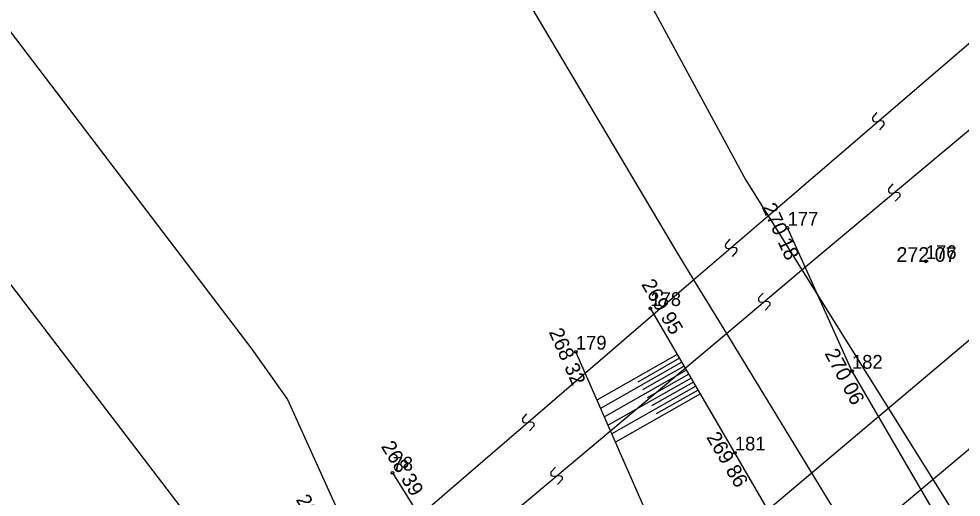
# Model space of a CAD drawing. Extents: x -492379 to -491966, y -1126153 to -1125860.
# Drawn here: x -492184.88 to -492154.06, y -1126013.22 to -1125997.58 of the extents above; entities that cross this region are included whole.
import ezdxf

# ---------------------------------------------------------------- set-up
doc = ezdxf.new("R2010")
doc.units = 0
for name, color, linetype in [('body', 7, 'Continuous'), ('hrana svahu', 7, 'Continuous'), ('katastrální mapa', 7, 'Continuous'), ('ostatní objekty', 7, 'Continuous'), ('podrobný výškový bod', 7, 'Continuous'), ('vodstvo', 7, 'Continuous'), ('výšky', 7, 'Continuous'), ('čísla bodů', 7, 'Continuous'), ('šrafy', 7, 'Continuous')]:
    doc.layers.add(name, color=color, linetype=linetype)

msp = doc.modelspace()

# ---------------------------------------------------------------- linework, layer by layer
at = {"layer": 'body'}
for p, q in [((-492159.736, -1126004.423), (-492159.736, -1126004.423)), ((-492155.216, -1126005.511), (-492155.216, -1126005.511)), ((-492164.225, -1126007.048), (-492164.225, -1126007.048)), ((-492166.662, -1126008.473), (-492166.662, -1126008.473)), ((-492157.632, -1126009.099), (-492157.632, -1126009.099)), ((-492161.461, -1126011.771), (-492161.461, -1126011.771)), ((-492172.655, -1126012.43), (-492172.655, -1126012.43))]:
    msp.add_line(p, q, dxfattribs=at)
at = {"layer": 'hrana svahu'}
for p, q in [((-492159.736, -1126004.423), (-492157.632, -1126009.099)), ((-492161.461, -1126011.771), (-492164.225, -1126007.048)), ((-492157.632, -1126009.099), (-492154.625, -1126014.262)), ((-492158.013, -1126017.698), (-492161.461, -1126011.771))]:
    msp.add_line(p, q, dxfattribs=at)
at = {"layer": 'katastrální mapa'}
for p, q in [((-492171.97, -1125982.8), (-492161.1, -1126002.86)), ((-492175.2, -1125985.26), (-492163.37, -1126005.2)), ((-492194.65, -1125985.54), (-492177.26, -1126008.38)), ((-492198.1, -1125989.34), (-492176.36, -1126017.77)), ((-492160.37, -1126004.02), (-492153.18, -1125997.84)), ((-492156.82, -1126000.65), (-492156.96, -1126000.81)), ((-492159.27, -1126005.79), (-492153.24, -1126000.74)), ((-492156.96, -1126000.81), (-492156.96, -1126000.89)), ((-492156.96, -1126000.89), (-492156.92, -1126000.94)), ((-492156.92, -1126000.94), (-492156.84, -1126000.95)), ((-492156.84, -1126000.95), (-492156.71, -1126000.91)), ((-492156.71, -1126000.91), (-492156.63, -1126000.92)), ((-492156.63, -1126000.92), (-492156.59, -1126000.97)), ((-492156.59, -1126000.97), (-492156.59, -1126001.05)), ((-492156.59, -1126001.05), (-492156.73, -1126001.21)), ((-492161.1, -1126002.86), (-492160.37, -1126004.02)), ((-492156.29, -1126002.98), (-492156.44, -1126003.14)), ((-492156.44, -1126003.14), (-492156.44, -1126003.23)), ((-492156.44, -1126003.23), (-492156.4, -1126003.27)), ((-492156.4, -1126003.27), (-492156.32, -1126003.28)), ((-492156.32, -1126003.28), (-492156.19, -1126003.25)), ((-492156.07, -1126003.39), (-492156.22, -1126003.55)), ((-492156.19, -1126003.25), (-492156.11, -1126003.26)), ((-492156.11, -1126003.26), (-492156.07, -1126003.3)), ((-492156.07, -1126003.3), (-492156.07, -1126003.39)), ((-492162.81, -1126006.12), (-492160.37, -1126004.02)), ((-492160.37, -1126004.02), (-492159.27, -1126005.79)), ((-492161.77, -1126004.95), (-492161.78, -1126005.03)), ((-492161.63, -1126004.79), (-492161.77, -1126004.95)), ((-492163.37, -1126005.2), (-492162.81, -1126006.12)), ((-492161.78, -1126005.03), (-492161.74, -1126005.08)), ((-492161.74, -1126005.08), (-492161.66, -1126005.09)), ((-492161.66, -1126005.09), (-492161.52, -1126005.05)), ((-492161.41, -1126005.19), (-492161.55, -1126005.35)), ((-492161.52, -1126005.05), (-492161.44, -1126005.06)), ((-492161.44, -1126005.06), (-492161.4, -1126005.11)), ((-492161.4, -1126005.11), (-492161.41, -1126005.19)), ((-492161.74, -1126007.87), (-492159.27, -1126005.79)), ((-492159.27, -1126005.79), (-492138.809, -1126038.508)), ((-492173.64, -1126015.43), (-492162.81, -1126006.12)), ((-492162.81, -1126006.12), (-492161.74, -1126007.87)), ((-492160.54, -1126006.55), (-492160.69, -1126006.71)), ((-492160.69, -1126006.71), (-492160.69, -1126006.79)), ((-492160.69, -1126006.79), (-492160.65, -1126006.84)), ((-492160.65, -1126006.84), (-492160.57, -1126006.85)), ((-492160.57, -1126006.85), (-492160.44, -1126006.81)), ((-492160.44, -1126006.81), (-492160.36, -1126006.82)), ((-492160.36, -1126006.82), (-492160.32, -1126006.87)), ((-492160.32, -1126006.87), (-492160.32, -1126006.95)), ((-492160.32, -1126006.95), (-492160.47, -1126007.11)), ((-492172.85, -1126017.18), (-492161.74, -1126007.87)), ((-492161.74, -1126007.87), (-492142.973, -1126038.587)), ((-492177.26, -1126008.38), (-492176.09, -1126010.03)), ((-492176.09, -1126010.03), (-492173.64, -1126015.43)), ((-492168.27, -1126010.5), (-492168.41, -1126010.65)), ((-492168.41, -1126010.65), (-492168.41, -1126010.74)), ((-492168.41, -1126010.74), (-492168.37, -1126010.78)), ((-492168.37, -1126010.78), (-492168.29, -1126010.79)), ((-492168.29, -1126010.79), (-492168.16, -1126010.76)), ((-492168.16, -1126010.76), (-492168.08, -1126010.77)), ((-492168.08, -1126010.77), (-492168.04, -1126010.81)), ((-492168.04, -1126010.81), (-492168.04, -1126010.9)), ((-492168.04, -1126010.9), (-492168.18, -1126011.05)), ((-492167.33, -1126012.24), (-492167.48, -1126012.4)), ((-492167.48, -1126012.4), (-492167.48, -1126012.49)), ((-492167.48, -1126012.49), (-492167.44, -1126012.53)), ((-492167.44, -1126012.53), (-492167.36, -1126012.54)), ((-492167.36, -1126012.54), (-492167.23, -1126012.51)), ((-492167.11, -1126012.65), (-492167.26, -1126012.81)), ((-492167.23, -1126012.51), (-492167.15, -1126012.52)), ((-492167.15, -1126012.52), (-492167.11, -1126012.56)), ((-492167.11, -1126012.56), (-492167.11, -1126012.65))]:
    msp.add_line(p, q, dxfattribs=at)
at = {"layer": 'ostatní objekty'}
for p, q in [((-492150.774, -1126005.547), (-492161.411, -1126014.509)), ((-492159.503, -1126016.42), (-492148.949, -1126007.574))]:
    msp.add_line(p, q, dxfattribs=at)
at = {"layer": 'podrobný výškový bod'}
for centre in [(-492159.736, -1126004.423), (-492155.216, -1126005.511), (-492164.225, -1126007.048), (-492166.662, -1126008.473), (-492157.632, -1126009.099), (-492161.461, -1126011.771), (-492172.655, -1126012.43)]:
    msp.add_circle(centre, 0.045, dxfattribs=at)
at = {"layer": 'vodstvo'}
for p, q in [((-492164.201, -1126014.074), (-492166.662, -1126008.473)), ((-492172.655, -1126012.43), (-492169.047, -1126018.211))]:
    msp.add_line(p, q, dxfattribs=at)
at = {"layer": 'šrafy'}
for p, q in [((-492163.344, -1126008.553), (-492165.971, -1126010.046)), ((-492163.268, -1126008.683), (-492164.633, -1126009.458)), ((-492163.193, -1126008.812), (-492165.85, -1126010.322)), ((-492163.117, -1126008.942), (-492164.483, -1126009.718)), ((-492163.041, -1126009.071), (-492165.728, -1126010.598)), ((-492162.889, -1126009.33), (-492165.607, -1126010.874)), ((-492162.965, -1126009.201), (-492164.334, -1126009.978)), ((-492162.738, -1126009.589), (-492165.486, -1126011.15)), ((-492162.814, -1126009.46), (-492164.185, -1126010.239)), ((-492162.586, -1126009.848), (-492165.364, -1126011.426)), ((-492162.662, -1126009.719), (-492164.036, -1126010.499))]:
    msp.add_line(p, q, dxfattribs=at)

# ---------------------------------------------------------------- texts
at = {"layer": 'výšky'}
for s, rotation, p in [('270 18', 294.4915, (-492160.589, -1126003.734)), ('269 95', 300.4511, (-492164.533, -1126006.264)), ('268 32', 293.7643, (-492167.553, -1126007.82)), ('270 06', 297.8375, (-492158.538, -1126008.521)), ('269 86', 300.2924, (-492162.407, -1126011.261)), ('268 39', 301.5258, (-492173.048, -1126011.563)), ('269 82', 300.2469, (-492175.83, -1126013.304))]:
    msp.add_text(s, height=0.48, rotation=rotation, dxfattribs=at).set_placement(p)
msp.add_text('272 07', height=0.48, dxfattribs=at).set_placement((-492156.176, -1126005.529))
at = {"layer": 'čísla bodů'}
for s, p in [('177', (-492159.736, -1126004.348)), ('176', (-492155.216, -1126005.436)), ('178', (-492164.225, -1126006.973)), ('179', (-492166.662, -1126008.398)), ('182', (-492157.632, -1126009.024)), ('181', (-492161.461, -1126011.696)), ('78', (-492172.655, -1126012.355))]:
    msp.add_text(s, height=0.45, dxfattribs=at).set_placement(p)

doc.saveas('drawing.dxf')
